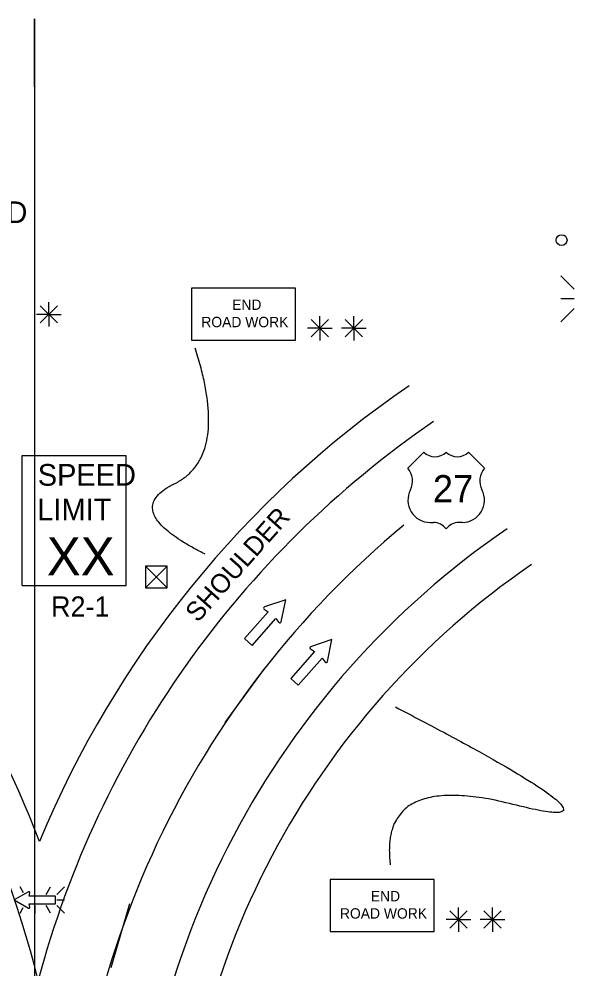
# Model space of a CAD drawing. Extents: x 16574 to 18479, y 5718 to 6974.
# Drawn here: x 16999 to 17204, y 6623.9 to 6974.1 of the extents above; entities that cross this region are included whole.
import ezdxf

# ---------------------------------------------------------------- set-up
doc = ezdxf.new("R2010")
doc.units = 0
for name, color, linetype in [('ALI_LEGAL_EX', 7, 'Continuous'), ('MT_SCRATCH_LEVEL_E', 7, 'Continuous'), ('PAVT_EDGE_EX', 7, 'Continuous'), ('TRAFFIC_SIGNS_PR', 7, 'Continuous'), ('TYPICAL_EX', 7, 'Continuous'), ('TYPICAL_TEXT_DIMEN_PR', 7, 'Continuous')]:
    doc.layers.add(name, color=color, linetype=linetype)

msp = doc.modelspace()

# ---------------------------------------------------------------- linework, layer by layer
at = {"layer": 'ALI_LEGAL_EX'}
for p, q in [((17004.68, 6974.12), (17004.68, 6155.98)), ((17004.68, 6877.04), (17004.68, 6013.12)), ((17039.84, 6647.53), (17032.85, 6623.88))]:
    msp.add_line(p, q, dxfattribs=at)
for points in [[(17004.68, 6949.12), (17004.68, 6974.12)], [(17075.14, 6714.42), (17089.89, 6734.61)]]:
    msp.add_lwpolyline(points, dxfattribs=at)
msp.add_arc((17357.65, 6525.15), 340, 129.5666, 180, dxfattribs=at)
at = {"layer": 'MT_SCRATCH_LEVEL_E'}
for p, q in [((17097.48, 6759.79), (17089.6, 6757.11)), ((17095.77, 6751.62), (17097.48, 6759.79)), ((17091.04, 6755.33), (17082.24, 6745.42)), ((17089.5, 6756.28), (17091.04, 6755.33)), ((17085.03, 6742.93), (17093.84, 6752.84)), ((17093.84, 6752.84), (17094.96, 6751.43)), ((17082.24, 6745.42), (17085.03, 6742.93)), ((17114.56, 6745.13), (17106.68, 6742.45)), ((17112.85, 6736.96), (17114.56, 6745.13)), ((17108.12, 6740.67), (17099.32, 6730.76)), ((17106.59, 6741.62), (17108.12, 6740.67)), ((17102.12, 6728.28), (17110.92, 6738.19)), ((17110.92, 6738.19), (17112.04, 6736.77)), ((17099.32, 6730.76), (17102.12, 6728.28))]:
    msp.add_line(p, q, dxfattribs=at)
for centre, start, end in [((17089.75, 6756.67), 108.8028, 238.3418), ((17095.31, 6751.73), 218.4141, 348.1511), ((17106.84, 6742.01), 108.8028, 238.3418), ((17112.4, 6737.07), 218.4141, 348.1511)]:
    msp.add_arc(centre, 0.463, start, end, dxfattribs=at)
at = {"layer": 'PAVT_EDGE_EX'}
for centre, radius, start, end in [((16629.65, 6525.15), 404, 21.0961, 66.0906), ((16629.65, 6525.15), 388, 14.0482, 66.0906), ((17357.65, 6525.15), 380, 124.3812, 157.5011), ((17357.65, 6525.15), 364, 124.3812, 165.0045), ((17357.65, 6525.15), 316, 124.3812, 180), ((17357.65, 6525.15), 300, 124.3812, 180)]:
    msp.add_arc(centre, radius, start, end, dxfattribs=at)
at = {"layer": 'TRAFFIC_SIGNS_PR'}
for p, q in [((17199.02, 6879.29), (17203.95, 6874.36)), ((17203.95, 6870.8), (17199.02, 6870.8)), ((17199.02, 6862.32), (17203.95, 6867.25)), ((17000.14, 6813), (17038.54, 6813)), ((17000.14, 6765), (17000.14, 6813)), ((17038.54, 6765), (17038.54, 6813)), ((17000.14, 6765), (17038.54, 6765)), ((17000.64, 6651.64), (16999.38, 6653.82)), ((17004.82, 6651.01), (17004.82, 6653.82)), ((17008.96, 6651.01), (17010.59, 6653.82)), ((17012.91, 6651.01), (17015.73, 6653.83)), ((17012.91, 6648.97), (17015.73, 6648.97)), ((16999.35, 6644.12), (17000.56, 6646.21)), ((17004.82, 6646.94), (17004.82, 6644.12)), ((17010.61, 6644.12), (17008.98, 6646.94)), ((17012.91, 6646.94), (17015.73, 6644.12))]:
    msp.add_line(p, q, dxfattribs=at)
for points in [[(17062.69, 6855.62), (17101.09, 6855.62), (17101.09, 6874.82), (17062.69, 6874.82)], [(17113.9, 6637.34), (17152.3, 6637.34), (17152.3, 6656.54), (17113.9, 6656.54)]]:
    msp.add_lwpolyline(points, close=True, dxfattribs=at)
for points in [[(17002.5, 6651.99), (16997.19, 6648.97), (17002.5, 6645.93)], [(17003, 6646.29), (17002.77, 6647.59), (17012.49, 6647.59), (17012.49, 6650.33), (17002.77, 6650.33), (17003, 6651.63)]]:
    msp.add_lwpolyline(points, dxfattribs=at)
msp.add_circle((17199.36, 6892.49), 2, dxfattribs=at)
for centre, start, end in [((17002.66, 6651.69), 350.7308, 118.8916), ((17002.66, 6646.23), 241.4833, 9.9593)]:
    msp.add_arc(centre, 0.341, start, end, dxfattribs=at)
at = {"layer": 'TYPICAL_EX'}
for p, q in [((17142.58, 6808.34), (17148.47, 6814.24)), ((17170.88, 6808.34), (17164.98, 6814.24)), ((17150.83, 6788.28), (17152, 6788.28)), ((17162.63, 6788.28), (17161.45, 6788.28))]:
    msp.add_line(p, q, dxfattribs=at)
for centre, radius, start, end in [((17152.6, 6818.53), 5.96, 226.1404, 313.8596), ((17160.86, 6818.53), 5.96, 226.1404, 313.8596), ((17136.99, 6803.62), 7.31, 333.0977, 40.1936), ((17176.46, 6803.62), 7.31, 139.8064, 206.9023), ((17150.84, 6796.53), 8.24, 152.6698, 269.9013), ((17162.62, 6796.53), 8.24, 270.0987, 27.3302), ((17152.02, 6782.38), 5.91, 37.1038, 90.1385), ((17161.44, 6782.38), 5.91, 89.8615, 142.8962)]:
    msp.add_arc(centre, radius, start, end, dxfattribs=at)
at = {"layer": 'TYPICAL_TEXT_DIMEN_PR'}
for p, q in [((17010.02, 6865.11), (17010.02, 6869.57)), ((17006.83, 6868.3), (17013.21, 6861.92)), ((17013.21, 6868.3), (17006.83, 6861.92)), ((17010.02, 6865.11), (17005.49, 6865.11)), ((17010.02, 6865.11), (17013.21, 6865.11)), ((17010.02, 6865.11), (17014.5, 6865.11)), ((17010.02, 6865.11), (17010.02, 6860.61)), ((17106.92, 6863.18), (17113.3, 6856.8)), ((17113.3, 6863.18), (17106.92, 6856.8)), ((17110.11, 6859.99), (17110.11, 6864.45)), ((17119.48, 6863.18), (17125.85, 6856.8)), ((17125.85, 6863.18), (17119.48, 6856.8)), ((17122.67, 6859.99), (17122.67, 6864.45)), ((17110.11, 6859.99), (17105.58, 6859.99)), ((17110.11, 6859.99), (17113.3, 6859.99)), ((17110.11, 6859.99), (17114.59, 6859.99)), ((17110.11, 6859.99), (17110.11, 6855.49)), ((17122.67, 6859.99), (17118.13, 6859.99)), ((17122.67, 6859.99), (17125.85, 6859.99)), ((17122.67, 6859.99), (17127.14, 6859.99)), ((17122.67, 6859.99), (17122.67, 6855.49)), ((17045.67, 6764.12), (17053.67, 6772.12)), ((17045.68, 6772.12), (17053.67, 6764.12)), ((17158.13, 6644.9), (17164.51, 6638.53)), ((17164.51, 6644.9), (17158.13, 6638.53)), ((17161.32, 6641.72), (17161.32, 6646.17)), ((17170.69, 6644.9), (17177.06, 6638.53)), ((17177.06, 6644.9), (17170.69, 6638.53)), ((17173.87, 6641.72), (17173.87, 6646.17)), ((17161.32, 6641.72), (17156.79, 6641.72)), ((17161.32, 6641.72), (17164.51, 6641.72)), ((17161.32, 6641.72), (17165.8, 6641.72)), ((17161.32, 6641.72), (17161.32, 6637.22)), ((17173.87, 6641.72), (17169.34, 6641.72)), ((17173.87, 6641.72), (17177.06, 6641.72)), ((17173.87, 6641.72), (17178.35, 6641.72)), ((17173.87, 6641.72), (17173.87, 6637.22))]:
    msp.add_line(p, q, dxfattribs=at)
msp.add_lwpolyline([(17045.68, 6772.12), (17045.67, 6764.12), (17053.67, 6764.12), (17053.67, 6772.12)], close=True, dxfattribs=at)
for points in [[(17067.74, 6776.56), (17035.79, 6792.58), (17076.97, 6812.63), (17064.02, 6852.67)], [(17138.01, 6720.2), (17233.21, 6670.88), (17131.63, 6697.14), (17136.1, 6661.91)]]:
    msp.add_open_spline(points, degree=2, dxfattribs=at)

# ---------------------------------------------------------------- texts
at = {"layer": 'TRAFFIC_SIGNS_PR'}
for s, height, p in [('SPEED', 8, (16965.8, 6898.79)), ('END', 3.831, (17077.69, 6866.75)), ('ROAD WORK', 3.831, (17066.3, 6860.36)), ('SPEED', 8, (17005.91, 6801.86)), ('LIMIT', 8, (17005.75, 6789.06)), ('XX', 14.031, (17009.25, 6768.76)), ('R2-1', 7.44, (17010.82, 6753.56)), ('END', 3.831, (17128.9, 6648.47)), ('ROAD WORK', 3.831, (17117.5, 6642.09))]:
    msp.add_text(s, height=height, dxfattribs=at).set_placement(p)
at = {"layer": 'TYPICAL_EX'}
msp.add_text('27', height=10, dxfattribs=at).set_placement((17151.84, 6795.77))
at = {"layer": 'TYPICAL_TEXT_DIMEN_PR'}
msp.add_text('SHOULDER', height=7, rotation=48.378, dxfattribs=at).set_placement((17065, 6751.09))

doc.saveas('drawing.dxf')
